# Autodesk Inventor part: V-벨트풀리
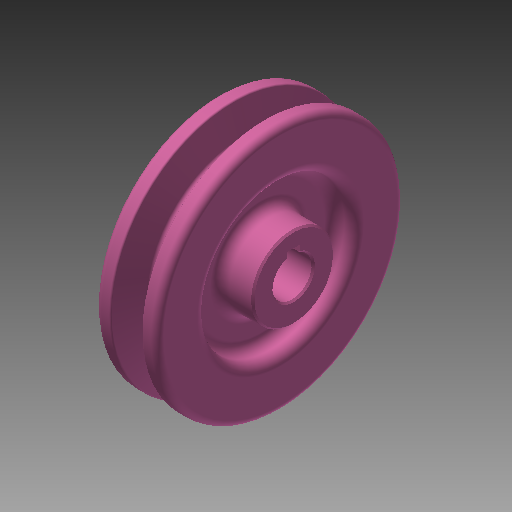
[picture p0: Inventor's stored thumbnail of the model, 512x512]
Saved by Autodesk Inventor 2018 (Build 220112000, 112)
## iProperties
Created: 2015-11
Part Number: V-벨트풀리
Material: 강철, 탄소
Document SubType Name: Modeling
Designer: mduedu
Density: 1 g/cm^3
Appearance: 분홍색
Author: mduedu
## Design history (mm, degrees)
sketch "스케치1"
  geometry: L1 (-9.5, 0)-(9.5, 0); L2 (0, 0)-(0, 37.7); L3 (-4.825, 37.7)-(-9.5, 37.7); L4 (-9.5, 37.7)-(-9.5, 0); L5 (0, 28.7)-(-2.074, 28.7); L6 (-2.074, 28.7)-(-4.825, 37.7); L7 (4.825, 37.7)-(9.5, 37.7); L8 (9.5, 37.7)-(9.5, 0); L9 (0, 28.7)-(2.074, 28.7); L10 (2.074, 28.7)-(4.825, 37.7); L11 (-9.5, 35)-(9.5, 35); 3 further points
  constraints: 22 end point, 7 point on line, 4 perpendicular, 3 symmetric about line, 1 coincident, 1 horizontal, 1 horizontal alignment, 1 midpoint, 1 vertical
  dimensions: "d0" = 19 distance of L1.start L1.end; "d2" = 75.4 diameter of L2.end L1 (derived); "d3" = 34 deg angle of L10 L6; "d4" = 6.3 distance between parallel lines of L11 L9; "d5" = 2.7 distance between parallel lines of L7 L11; "d6" = 8 distance of point (4, 35) point (-4, 35); "d7" = 70 diameter of L11 L1
revolve "회전1" sketch "스케치1" stored, may be unused: angle "d8" = 90 deg
sketch "스케치2"
  geometry: C1 r 22.5 at (0, 0); C2 r 12.5 at (0, 0); C3 r 37.7 at (0, 0) reference; 1 further point
  constraints: 2 centre point, 2 coincident
  dimensions: "d35" = 15.2 radial gap between concentric circles of C3 C1 (computed from d5); "d36" = 10 radial gap between concentric circles of C1 C2
extrude "돌출1" cut sketch "스케치2" distance "d11" = 6; taper "d12" = 0 deg
fillet "모깎기1" dims "d13" = 3
feature "면 이동1"
fillet "모깎기2" dims "d14" = 3
fillet "모깎기3" dims "d15" = 1, "d16" = 0.5, "d17" = 2
hole "구멍1" diameter "d20" = 12; stored, may be unused: countersink angle "d24" = 90 deg, drill point angle "d26" = 118 deg; dims "d21" = 6, "d22" = 4, "d23" = 2, "d25" = 8, "d37" = 10, "d38" = 10
sketch "스케치3"
  geometry: L1 (-2, 0)-(2, 0); L2 (2, 0)-(2, 7.8); L3 (2, 7.8)-(-2, 7.8); L4 (-2, 7.8)-(-2, 0); C1 r 12.5 at (0, 0) reference; 2 further points
  constraints: 8 end point, 2 coincident, 2 parallel, 1 horizontal, 1 midpoint, 1 perpendicular
  dimensions: "d27" = 4 distance of L2.end L3.end; "d29" = 7.8 distance of L3.end L1.start
extrude "돌출2" cut sketch "스케치3" extent not by distance; stored distance "d30" = 6; taper "d31" = 0 deg
chamfer "모따기1" distance "d32" = 0.5; stored, may be unused: second distance "d33" = 2, angle "d34" = 45 deg
node "솔리드1"
mirror "대칭1"
